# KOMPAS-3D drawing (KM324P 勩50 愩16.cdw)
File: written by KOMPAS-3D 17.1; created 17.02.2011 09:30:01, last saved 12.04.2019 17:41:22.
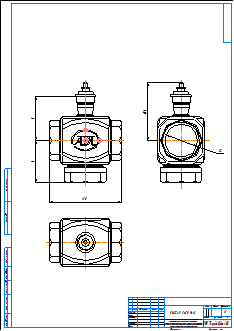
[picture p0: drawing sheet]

Title block, sheet 1: name: KM324P Ду50 Ру16; material: Внимание! Данный продукт является объектом авторского права ООО «Торговый Дом АДЛ». / Запрещается изменение, копирование, распространение / (в том числе путем копирования на другие сайты и ресурсы в Интернете) / или любое иное использование информации и объектов без предварительного / согласия правообладателя (ООО «Торговый Дом АДЛ»).; scale: 1:1; sheets: 1; organisation: ООО "Торговый дом АДЛ"; sheet format: A2; stored path: \\adlc.lan\data\АДЛ_ПКД\3D-модели\ADL production\Клапаны ГРАНРЕГ\Трёхходовой клапан KM324P\KOMPAS 2D\KM324P Ду50 Ру16.cdw

Views: Спереди 1, Проекционный вид 2, Проекционный вид 3, Спереди 4, Проекционный вид 5, Проекционный вид 6
Dimensions and other numbers on the sheet: 130; 79; 76; 104; 1:1; 1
